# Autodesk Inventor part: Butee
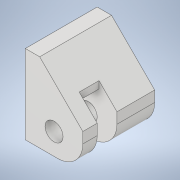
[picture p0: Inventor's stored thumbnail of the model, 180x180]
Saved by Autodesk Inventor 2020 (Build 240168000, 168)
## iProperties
Created: 2018-06
Part Number: Butee
Material: Plastique ABS
Document SubType Name: Modeling
Designer: Fabian Perrée
Density: 1.06 g/cm^3
Appearance: Lisse - Blanc
Author: Fabian Perrée
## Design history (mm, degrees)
sketch "Esquisse1"
  geometry: L1 (0, 0)-(0, 13); L2 (0, 22)-(4, 22); L3 (4, 22)-(11, 15); L4 (16, 10)-(16, 7); L5 (9, 0)-(0, 0); L6 (0, 13)-(11, 13); L7 (11, 13)-(11, 15); L8 (11, 15)-(16, 10); L9 (0, 13)-(0, 22); C1 r 2.5 at (8, 6); A1 r 7 centre (9, 7) between (9, 0) and (16, 7); 1 further point
  constraints: 18 end point, 4 perpendicular, 2 centre point, 2 parallel, 2 point on circle, 2 point on line, 2 tangent, 2 vertical, 1 collinear, 1 horizontal
  dimensions: "d1" = 4 distance of L2.start L2.end; "d2" = 135 deg angle of L2 L3; "d3" = 5 diameter of C1; "d4" = 6 distance from line of L5 C1.centre; "d5" = 8 distance from line of L1 C1.centre; "d7" = 7 radius of A1; "d9" = 3 distance from line of C1.centre L7; "d18" = 13 distance between parallel lines of L5 L6; "d20" = 16 distance from line of L2 C1.centre; "d21" = 16 distance between parallel lines of L4 L1
extrude "Extrusion1" new body sketch "Esquisse1" distance "d10" = 4; taper "d12" = 0 deg; dims "d11" = 16, "d13" = 0
extrude "Extrusion2" join sketch "Esquisse1" distance "d14" = 4; taper "d15" = 0 deg
node "Plan de construction1"
node "Plan de construction2"
extrude "Extrusion3" join sketch "Esquisse1" stored distance "d16" = 10; taper "d17" = 0 deg
node "Solide1"
other parameters: "d19" = 5.5
